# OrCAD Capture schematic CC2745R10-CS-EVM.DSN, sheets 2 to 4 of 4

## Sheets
2 2_Peripherals: size A3
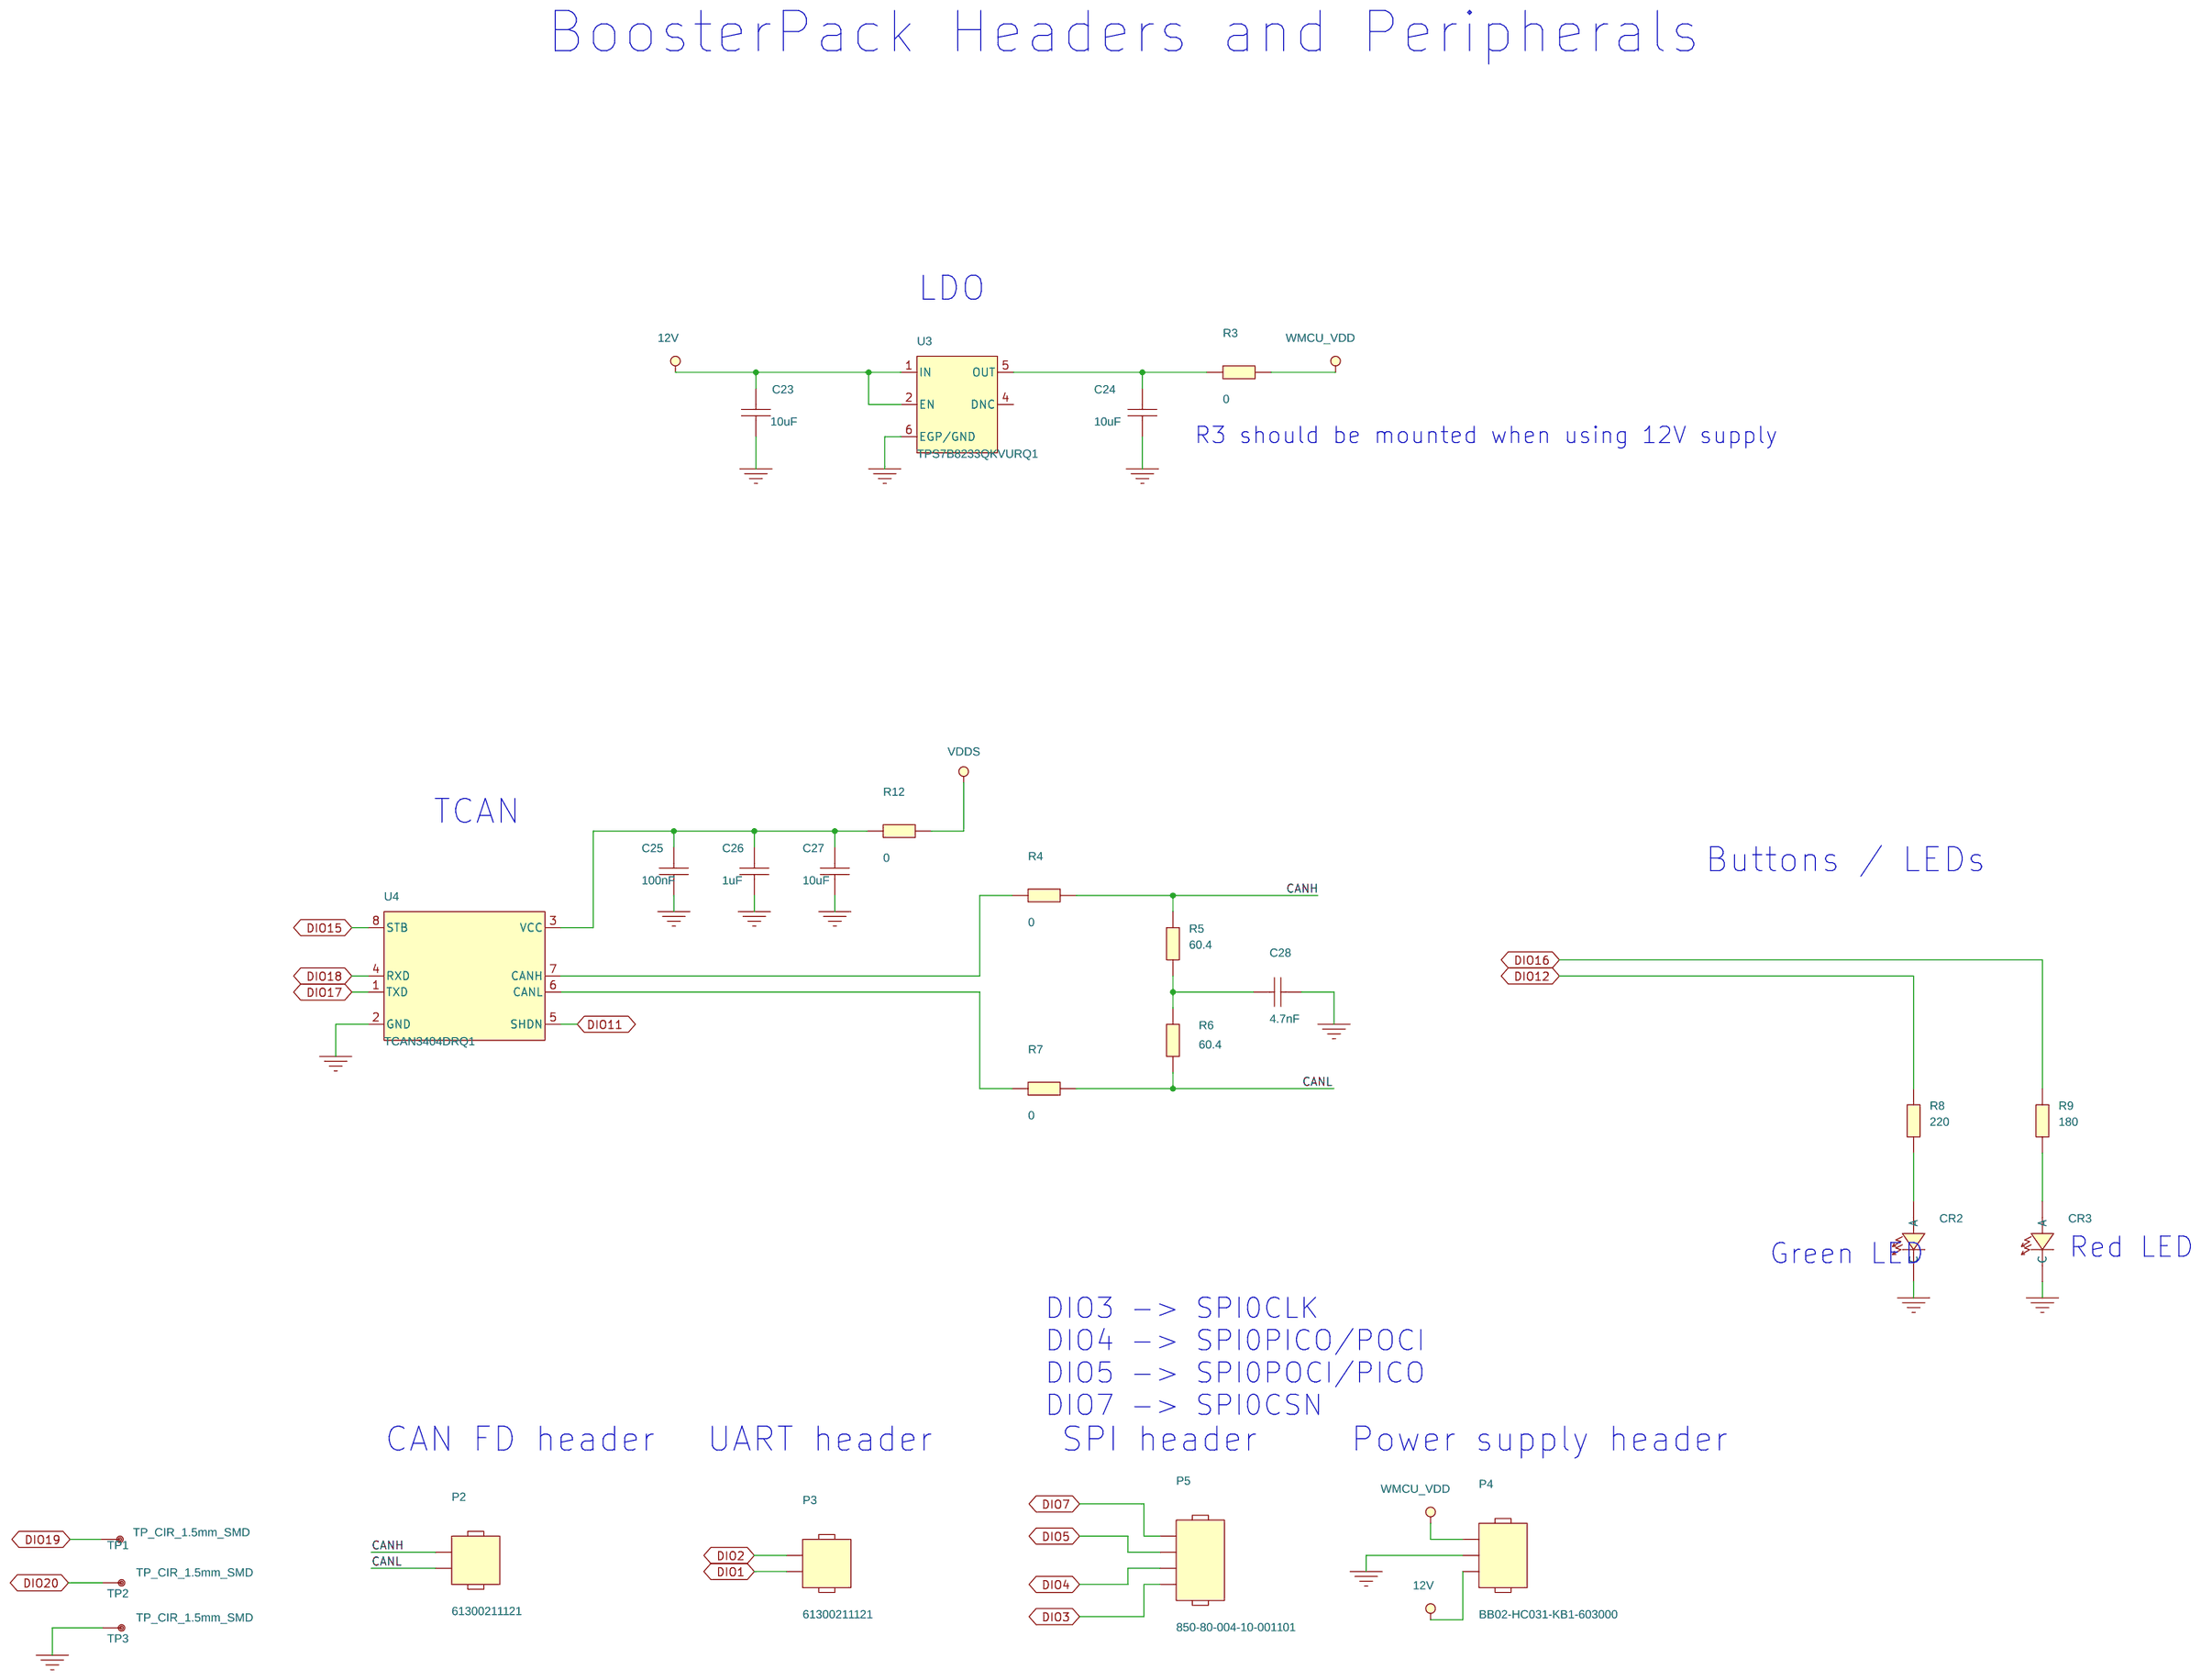
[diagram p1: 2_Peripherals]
3 3_Debugger Interface: size A3
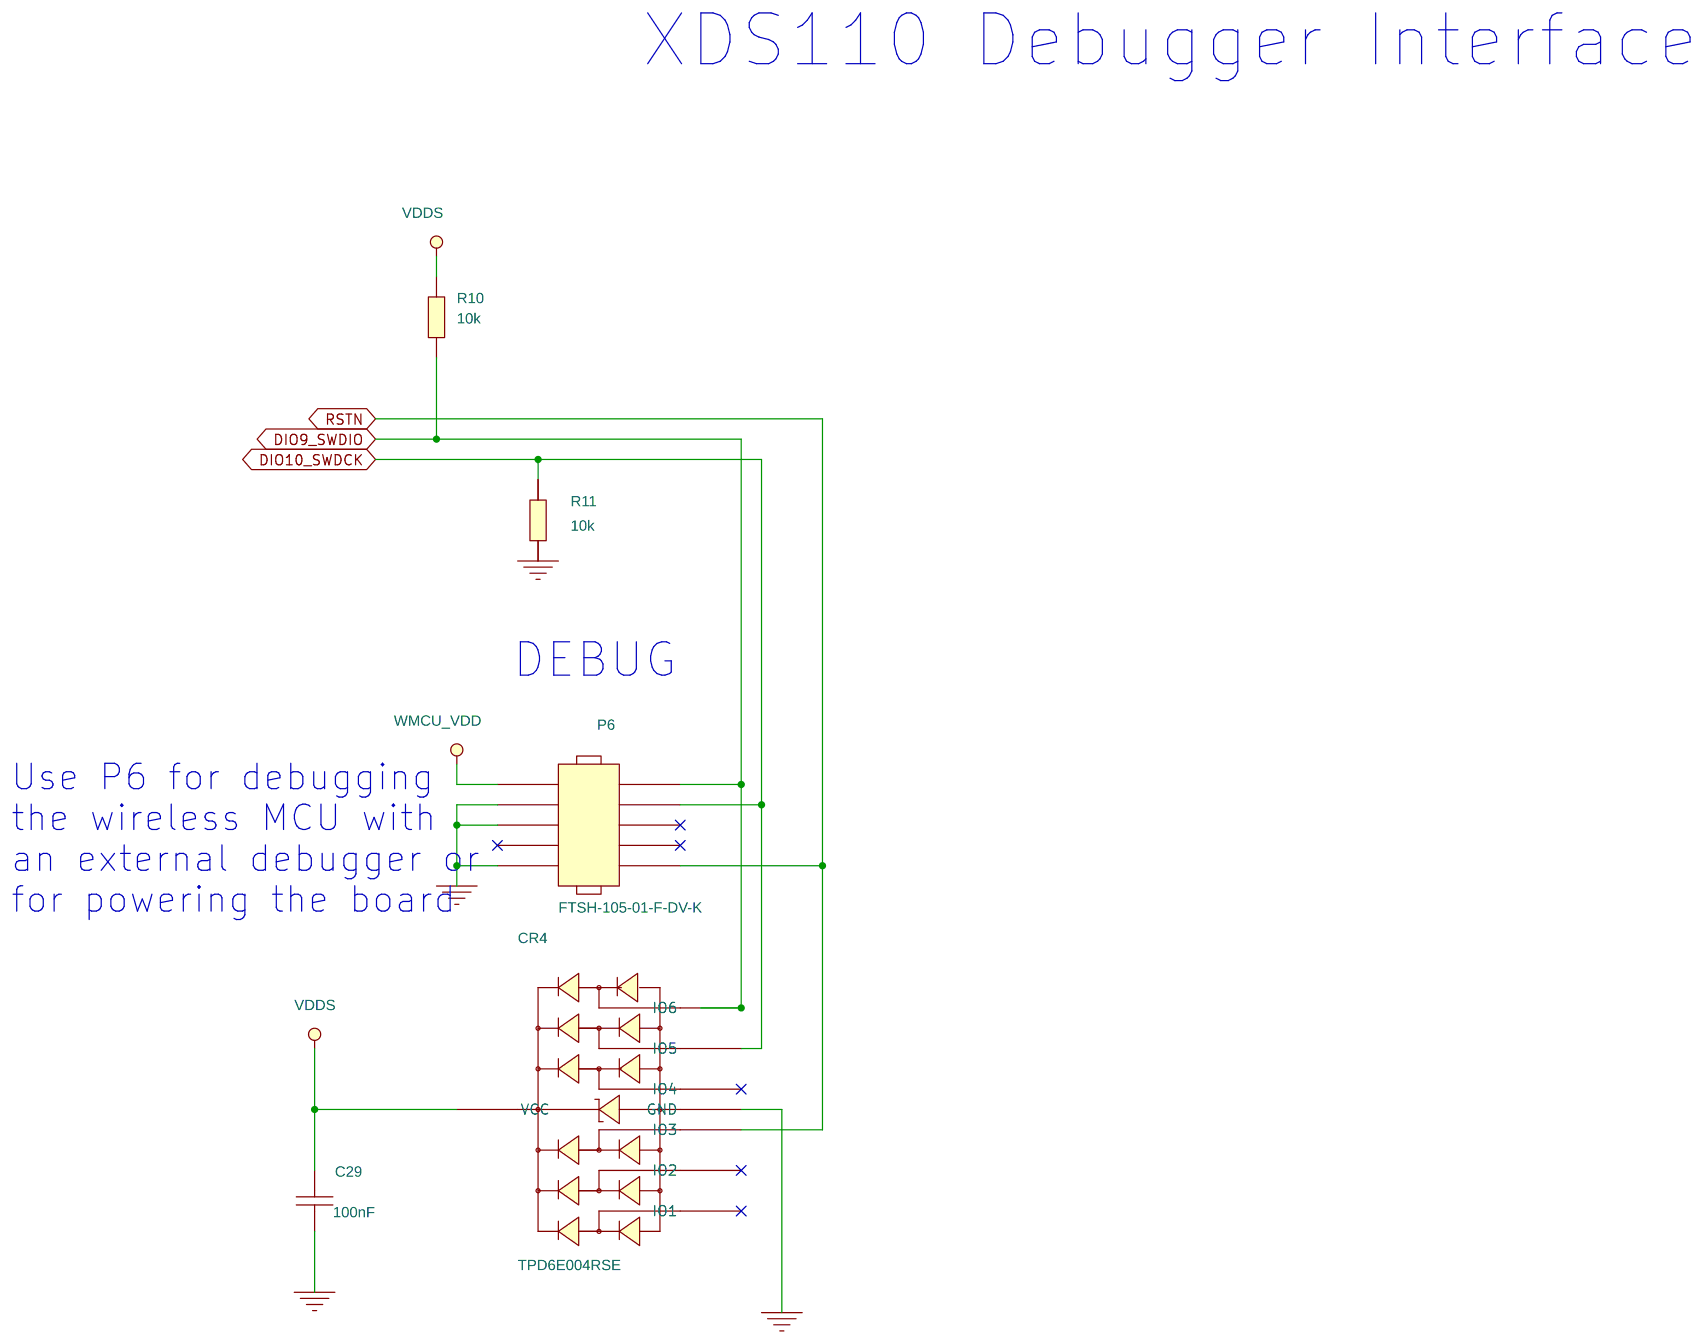
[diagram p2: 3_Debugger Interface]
4 4_Mech: size A3
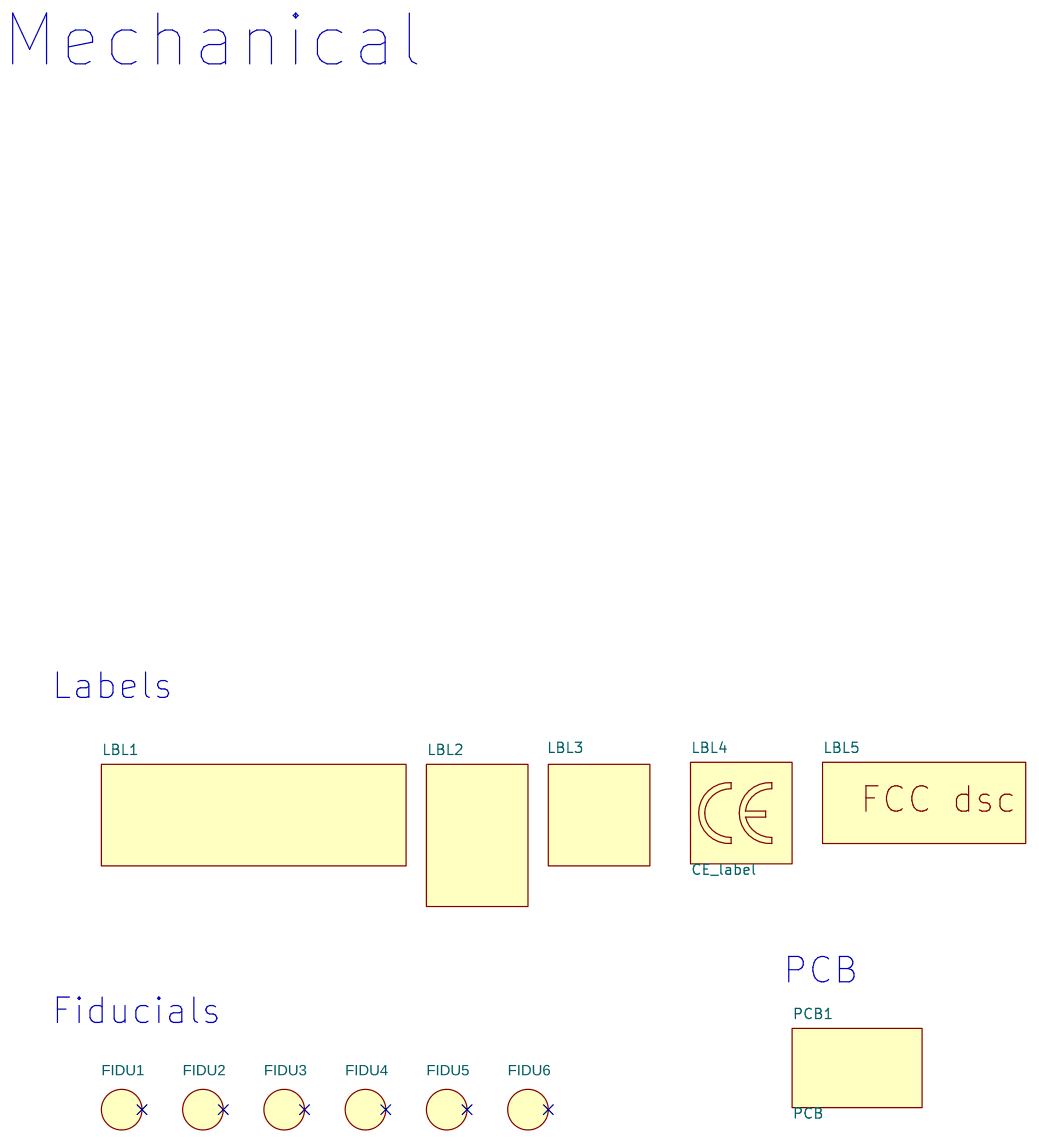
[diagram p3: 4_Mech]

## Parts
sheet 2_Peripherals
C23  10uF  [CAPC2012X150A2N]
C24  10uF  [CAPC1608X100A2N]
C25  100nF  [CAPC0603X35B2N]
C26  1uF  [CAPC1005X60B2N]
C27  10uF  [CAPC1608X100A2N]
C28  4.7nF  [CAPC1005X60A2N]
CR2  150060VS55040  [LEDC1608X50F2N]
CR3  150060RS55040  [LEDC1608X50F2N]
P2  61300211121  [WURTH_61300211121_A2B]
P3  61300211121  [WURTH_61300211121_A2B]
P4  BB02-HC031-KB1-603000  [GRADCONN_BB02HC031KB1603000_A2B]
P5  850-80-004-10-001101  [PRECIDIP_8508000410001101_A2B]
R3  0  [RESC1608X55A2N]
R4  0  [RESC0603X35B2N]
R5  60.4  [RESC1005X40A2N]
R6  60.4  [RESC1005X40A2N]
R7  0  [RESC0603X35B2N]
R8  220  [RESC1005X40B2N]
R9  180  [RESC1005X40B2N]
R12  0  [RESC0603X35B2N]
TP1  TP_CIR_1.5mm_SMD  [TP1500]
TP2  TP_CIR_1.5mm_SMD  [TP1500]
TP3  TP_CIR_1.5mm_SMD  [TP1500]
U3  TPS7B8233QKVURQ1  [TO114P1011X252-6_5A2N]
U4  TCAN3404DRQ1  [SOIC127P600X175-8A2N]
sheet 3_Debugger Interface
C29  100nF  [CAPC0603X35B2N]
CR4  TPD6E004RSE  [QFNFC50P150X150X60-8A2N]
P6  FTSH-105-01-F-DV-K  [SAMTEC_FTSH-105-01-F-DV-K-10N]
R10  10k  [RESC1005X40B2N]
R11  10k  [RESC1005X40B2N]
sheet 4_Mech
FIDU1  FIDU_1.27mm  [FID127X142]
FIDU2  FIDU_1.27mm  [FID127X142]
FIDU3  FIDU_1.27mm  [FID127X142]
FIDU4  FIDU_1.27mm  [FID127X142]
FIDU5  FIDU_1.27mm  [FID127X142]
FIDU6  FIDU_1.27mm  [FID127X142]
LBL1  TI_LOGO  [TI_LOGO_1]
LBL2  TRASH_7mm  [TRASH_7MM]
LBL3  ESD_LABEL_5x5mm  [ESD_LABEL_5X5]
LBL4  CE_label  [CE_MARKING]
LBL5  LABEL_FOR_EVALUATION_ONLY  [LABEL_FOR_EVALUATION_ONLY]
PCB1  PCB  [TI_MCUXX]

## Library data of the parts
C23 = CAPACITOR: CAPACITOR, CERAMIC X7S, 10uF, 25V, -10%/+10%, -55DEGC/+125DEGC, 0805, SMD; ALT_SYMBOLS: CAPC2012X150A2L,CAPC2012X150A2M; Additional Datasheet URL: https://product.samsungsem.com/mlcc/CL21Y106KABVPN.do; Budgetary Price: .181 USD; Country of Origin: China, South Korea; Datasheet URL: https://www.samsungsem.com/resources/file/global/support/product_catalog/MLCC_Automotive.pdf; Dielectric Type: X7S; Lead Time: 20; Mass: N/A; Maximum Operating Temperature: +125DEGC; Maximum Tolerance: +10%; Minimum Operating Temperature: -55DEGC; Minimum Tolerance: -10%; Mounting Type: SMD; NOTEfied URL: https://dev-webinterface.dpserver.no/item/61932654; PCB Package: 0805; Packing Size: 2000; Packing Type: Tape & Reel; Part Number: 02-11587; Part Type: Capacitor|CERAMIC|0805|STANDARD; REACH/SVHC Details: SVHC List Version; ROHS: Compliant; Rated Voltage: 25V; Status: Released; Type: Capacitor; Vendor: SAMSUNG ELECTRO-MECHANICS; Vendor Part Number: CL21Y106KABVPNE; Vendor Part Status: Active
C24 C27 = CAPACITOR: CAPACITOR, CERAMIC X7T, 10uF, 10V, -20%/+20%, -55DEGC/+125DEGC, 0603, SMD; ALT_SYMBOLS: CAPC1608X100A2L,CAPC1608X100A2M; Additional Datasheet URL: https://www.murata.com/en-eu/products/productdetail?partno=GRT188D71A106ME13%23; Country of Origin: Missing Info; Datasheet URL: https://search.murata.co.jp/Ceramy/image/img/A01X/G101/ENG/GRT188D71A106ME13-01A.pdf; Dielectric Type: X7T; Mass: 0.0091g; Maximum Operating Temperature: +125DEGC; Maximum Tolerance: +20%; Minimum Operating Temperature: -55DEGC; Minimum Tolerance: -20%; Mounting Type: SMD; NOTEfied URL: https://notefied-dynamic-precision.com/NOTEfiedWebInterface/part/show?partNumber=02-10485; PCB Package: 0603; Packing Size: 4000; Packing Type: Tape & Reel; Part Number: 02-10485; Part Type: Capacitor|CERAMIC|0603|STANDARD; REACH/SVHC Compliance: Compliant; REACH/SVHC Details: SVHC List Version Jul 08, 2021; REACH/SVHC Source: REACH Declaration; REACH/SVHC Status: Unaffected; ROHS: Compliant; Rated Voltage: 10V; Revision: R010; Status: Released; Texas Part Status: Under Review; Type: Capacitor; Vendor: MURATA; Vendor Part Number: GRT188D71A106ME13D; Vendor Part Status: Active
C25 C29 = CAPACITOR: CAPACITOR, CERAMIC X8M, 100nF, 10V, -10%/+10%, -55DEGC/+150DEGC, 0201, SMD; ALT_SYMBOLS: CAPC0603X35B2L,CAPC0603X35B2M; Additional Datasheet URL: https://www.murata.com/en-us/products/productdetail?partno=GCM033M8ED104KE07%23; Budgetary Price: .01502 USD; Country of Origin: Missing Info; Datasheet URL: https://search.murata.co.jp/Ceramy/image/img/A01X/G101/ENG/GCM033M8ED104KE07-01A.pdf; Dielectric Type: X8M; Lead Time: 23; Mass: 0.00033g; Maximum Operating Temperature: +150DEGC; Maximum Tolerance: +10%; Minimum Operating Temperature: -55DEGC; Minimum Tolerance: -10%; Mounting Type: SMD; NOTEfied URL: https://dev-webinterface.dpserver.no/item/60514337; PCB Package: 0201; Packing Size: 15000; Packing Type: Tape & Reel; Part Number: 02-11497; Part Type: Capacitor|CERAMIC|0201|STANDARD; ROHS: Compliant; Rated Voltage: 10V; Status: Released; Texas Part Status: Under Review; Type: Capacitor; Vendor: MURATA; Vendor Part Number: GCM033M8ED104KE07D; Vendor Part Status: Active
C26 = CAPACITOR: CAPACITOR, CERAMIC X7R, 1uF, 6.3V, -10%/+10%, -55DEGC/+125DEGC, 0402, SMD; Additional Datasheet URL: https://www.murata.com/en-eu/products/productdetail?partno=GRT155R70J105KE01%23; Country of Origin: Missing Info; Datasheet URL: https://search.murata.co.jp/Ceramy/image/img/A01X/G101/ENG/GRT155R70J105KE01-01A.pdf; Dielectric Type: X7R; Mass: 0.0016g; Maximum Operating Temperature: +125DEGC; Maximum Tolerance: +10%; Minimum Operating Temperature: -55DEGC; Minimum Tolerance: -10%; Mounting Type: SMD; NOTEfied URL: https://notefied-dynamic-precision.com/NOTEfiedWebInterface/part/show?partNumber=02-10519; PCB Package: 0402; Packing Size: 10000; Packing Type: Tape & Reel; Part Number: 02-10519; Part Type: Capacitor|CERAMIC|0402|STANDARD; REACH/SVHC Compliance: Compliant; REACH/SVHC Details: SVHC List Version Jul 08, 2021; REACH/SVHC Source: REACH Declaration; REACH/SVHC Status: Unaffected; ROHS: Compliant; Rated Voltage: 6.3V; Revision: R010; Status: Released; Texas Part Status: Under Review; Type: Capacitor; Vendor: MURATA; Vendor Part Number: GRT155R70J105KE01D; Vendor Part Status: Active
C28 = CAPACITOR: CAPACITOR, CERAMIC X7R, 4.7nF, 50V, -10%/+10%, -55DEGC/+125DEGC, 0402, SMD; ALT_SYMBOLS: CAPC1005X60A2L,CAPC1005X60A2M; Additional Datasheet URL: https://www.murata.com/en-us/products/productdetail?partno=GCM155R71H472KA37%23; Budgetary Price: .00716 USD; Country of Origin: China, Japan; Datasheet URL: https://search.murata.co.jp/Ceramy/image/img/A01X/G101/ENG/GCM155R71H472KA37-01A.pdf; Dielectric Type: X7R; Lead Time: 15; Mass: 0.0016g; Maximum Operating Temperature: +125DEGC; Maximum Tolerance: +10%; Minimum Operating Temperature: -55DEGC; Minimum Tolerance: -10%; Mounting Type: SMD; NOTEfied URL: https://dev-webinterface.dpserver.no/item/14049570; PCB Package: 0402; Packing Size: 10000; Packing Type: Tape & Reel; Part Number: 02-08594; Part Type: Capacitor|CERAMIC|0402|STANDARD; ROHS: Compliant; Rated Voltage: 50V; Status: Released; Type: Capacitor; Vendor: MURATA; Vendor Part Number: GCM155R71H472KA37D; Vendor Part Status: Active
CR2 = LED: OPTO, LED, AlInGaP, GREEN, STRAIGHT, 573nm, 2V, 0.02A, 0.048W, 0603, SMD; ALT_SYMBOLS: LEDC1608X50F2L,LEDC1608X50F2M; Additional Datasheet URL: https://www.we-online.com/en/components/products/WL-SMCD#150060VS55040; Country of Origin: Missing Info; Datasheet URL: https://www.we-online.com/en/components/products/datasheet/150060VS55040.pdf; Mass: N/A; Maximum Operating Temperature: +85DEGC; Minimum Operating Temperature: -40DEGC; Mounting Type: SMD; NOTEfied URL: https://notefied-dynamic-precision.com/NOTEfiedWebInterface/part/show?partNumber=15-03575; PCB Package: 0603; Packing Size: 4000; Packing Type: Tape & Reel; Part Number: 15-03575; Part Type: Opto|LED|0603; REACH/SVHC Details: SVHC List Version; ROHS: Compliant; Rated Current: 0.02A; Rated Power: 0.048W; Rated Voltage: 2V; Revision: R008; Status: Released; Type: Opto; Vendor: WURTH; Vendor Part Status: Active
CR3 = LED: OPTO, LED, AlInGaP, RED, STRAIGHT, 624nm, 2V, 0.02A, 0.048W, 0603, SMD; ALT_SYMBOLS: LEDC1608X50F2L,LEDC1608X50F2M; Additional Datasheet URL: https://www.we-online.com/en/components/products/WL-SMCD#150060RS55040; Country of Origin: Missing Info; Datasheet URL: https://www.we-online.com/en/components/products/datasheet/150060RS55040.pdf; Mass: N/A; Maximum Operating Temperature: +85DEGC; Minimum Operating Temperature: -40DEGC; Mounting Type: SMD; NOTEfied URL: https://notefied-dynamic-precision.com/NOTEfiedWebInterface/part/show?partNumber=15-03577; PCB Package: 0603; Packing Size: 4000; Packing Type: Tape & Reel; Part Number: 15-03577; Part Type: Opto|LED|0603; REACH/SVHC Details: SVHC List Version; ROHS: Compliant; Rated Current: 0.02A; Rated Power: 0.048W; Rated Voltage: 2V; Revision: R008; Status: Released; Type: Opto; Vendor: WURTH; Vendor Part Status: Active
P2 P3 = CONN_HEADER_2_P_S: CONNECTOR, HEADER, MALE, STRAIGHT, 1 ROW(S), 2 PIN(S), PITCH 2.54mm, PTH; ALT_SYMBOLS: WURTH_61300211121_A2A,WURTH_61300211121_A2C; Additional Datasheet URL: https://www.we-online.com/en/components/products/PHD_2_54_THT_PIN_HEADER_6130XX11121?sq=61300211121#61300211121; Budgetary Price: .06 USD; Country of Origin: Taiwan; Datasheet URL: https://www.we-online.com/components/products/datasheet/61300211121.pdf; Lead Time: 13; Mass: N/A; Maximum Operating Temperature: +105DEGC; Minimum Operating Temperature: -40DEGC; Mounting Type: PTH; NOTEfied URL: https://dev-webinterface.dpserver.no/item/62668710; Number of Positions: 2; Number of Rows: 1; Packing Size: 1000; Packing Type: Bag; Part Number: 06-16671; Part Type: Connector|HEADER|STANDARD; Pitch: 2.54mm; REACH/SVHC Compliance: Compliant; REACH/SVHC Details: SVHC List Version Nov 07, 2024 (242); REACH/SVHC Source: REACH Declaration; REACH/SVHC Status: Unaffected; ROHS: Compliant; Rated Current: 3A; Rated Voltage: 250V; Status: Released; Texas Part Status: Under Review; Type: Connector; Vendor: WURTH; Vendor Part Status: Active
P4 = CONN_HEADER_3_P_S: CONNECTOR, HEADER, MALE, STRAIGHT, 1 ROW(S), 3 PIN(S), PITCH 2.54mm, PTH; ALT_SYMBOLS: GRADCONN_BB02HC031KB1603000_A2A,GRADCONN_BB02HC031KB1603000_A2C; Additional Datasheet URL: https://www.gradconn.com/Products/BoardToBoard/All/BB02-HC; Country of Origin: Missing Info; Datasheet URL: https://www.gradconn.com/files/Drawings/BB02-HC.pdf; Mass: N/A; Maximum Operating Temperature: +105DEGC; Minimum Operating Temperature: -40DEGC; Mounting Type: PTH; NOTEfied URL: https://dev-webinterface.dpserver.no/item/7324030; Number of Positions: 3; Number of Rows: 1; Packing Size: N/A; Packing Type: Missing Info; Part Number: 06-05038; Part Type: Connector|HEADER|STANDARD; Pitch: 2.54mm; REACH/SVHC Compliance: Compliant; REACH/SVHC Details: SVHC List Version Jun 20, 2016 (169); REACH/SVHC Source: RoHS & REACH Declaration; REACH/SVHC Status: Unaffected; ROHS: Compliant; Rated Current: 3A; Rated Voltage: 250V; Status: Released; Texas Part Status: Under Review; Type: Connector; Vendor: GRADCONN; Vendor Part Status: Active
P5 = CONN_HEADER_4_P_S: CONNECTOR, HEADER, MALE, STRAIGHT, 1 ROW(S), 4 PIN(S), PITCH 1.27mm, PTH; ALT_SYMBOLS: PRECIDIP_8508000410001101_A2A,PRECIDIP_8508000410001101_A2C; Additional Datasheet URL: https://precidip.com/product/850-80-004-10-001101/; Budgetary Price: .5229 USD; Country of Origin: Switzerland; Datasheet URL: https://precidip.com/wp-content/uploads/2024/10/Full-English.pdf; Lead Time: 11; Mass: N/A; Maximum Operating Temperature: +125DEGC; Minimum Operating Temperature: -55DEGC; Mounting Type: PTH; NOTEfied URL: https://dev-webinterface.dpserver.no/item/62648482; Number of Positions: 4; Number of Rows: 1; Packing Size: N/A; Packing Type: Missing Info; Part Number: 06-16651; Part Type: Connector|HEADER|STANDARD; Pitch: 1.27mm; REACH/SVHC Compliance: Non-Compliant; REACH/SVHC Details: SVHC List Version Jan 21, 2025 (247); REACH/SVHC Source: REACH Declaration; REACH/SVHC Status: Affected; ROHS: Compliant; Rated Current: 1A; Rated Voltage: N/A; Status: Released; Texas Part Status: Under Review; Type: Connector; Vendor: PRECI-DIP; Vendor Part Status: Active
R3 = RESISTOR: RESISTOR, THICK FILM, JUMPER, 0, 0R/+0.05R, 0.1W, 1A, -55DEGC/+155DEGC, 0603, SMD; ALT_SYMBOLS: RESC1608X55A2L,RESC1608X55A2M; Additional Datasheet URL: https://www.yageo.com/en/ProductSearch/PartNumberSearch?part_number=AC0603JR-070RL; Budgetary Price: .00383 USD; Country of Origin: China, Taiwan; Datasheet URL: https://www.yageo.com/upload/media/product/productsearch/datasheet/rchip/PYu-AC_51_RoHS_L_11.pdf; Lead Time: 18; Mass: N/A; Maximum Operating Temperature: +155DEGC; Maximum Temperature Coefficient: N/A; Maximum Tolerance: +0.05R; Minimum Operating Temperature: -55DEGC; Minimum Temperature Coefficient: N/A; Minimum Tolerance: 0R; Mounting Type: SMD; NOTEfied URL: https://dev-webinterface.dpserver.no/item/58001233; PCB Package: 0603; Packing Size: 5000; Packing Type: Tape & Reel; Part Number: 01-26111; Part Type: Resistor|0603|JUMPER; REACH/SVHC Details: SVHC List Version; ROHS: Exempt; Rated Current: 1A; Rated Power: 0.1W; Rated Voltage: N/A; Resistor Type: THICK FILM; Status: Released; Type: Resistor; Vendor: YAGEO; Vendor Part Number: AC0603JR-070RL; Vendor Part Status: Active
R4 R7 R12 = RESISTOR: RESISTOR, THICK FILM, JUMPER, 0, 0R/+0.05R, 0.05W, 0.5A, -55DEGC/+155DEGC, 0201, SMD; ALT_SYMBOLS: RESC0603X35B2L,RESC0603X35B2M; Additional Datasheet URL: https://www.yageo.com/en/Home; Budgetary Price: .01936 USD; Country of Origin: Missing Info; Datasheet URL: https://www.yageo.com/upload/media/product/productsearch/datasheet/rchip/PYu-AF_51_RoHS_L_10.pdf; Lead Time: 18; Mass: N/A; Maximum Operating Temperature: +155DEGC; Maximum Temperature Coefficient: N/A; Maximum Tolerance: +0.05R; Minimum Operating Temperature: -55DEGC; Minimum Temperature Coefficient: N/A; Minimum Tolerance: 0R; Mounting Type: SMD; NOTEfied URL: https://dev-webinterface.dpserver.no/item/59954582; PCB Package: 0201; Packing Size: 50000; Packing Type: Tape & Reel; Part Number: 01-26238; Part Type: Resistor|0201|JUMPER; ROHS: Exempt; Rated Current: 0.5A; Rated Power: 0.05W; Resistor Type: THICK FILM; Status: Released; Texas Part Status: Under Review; Type: Resistor; Vendor: YAGEO; Vendor Part Number: AF0201JR-130RL; Vendor Part Status: Active
R5 R6 = RESISTOR: RESISTOR, THICK FILM, 60.4, -1%/+1%, 0.1W, 50V, -55DEGC/+155DEGC, 0402, SMD; ALT_SYMBOLS: RESC1005X40A2L,RESC1005X40A2M; Additional Datasheet URL: https://industrial.panasonic.com/ww/products/pt/general-purpose-chip-resistors/models/ERJ2RKF60R4X; Budgetary Price: .00413 USD; Country of Origin: Japan; Datasheet URL: https://industrial.panasonic.com/cdbs/www-data/pdf/RDA0000/AOA0000C304.pdf; Lead Time: 11; Mass: 0.0008g; Maximum Operating Temperature: +155DEGC; Maximum Temperature Coefficient: +100PPM/DEGC; Maximum Tolerance: +1%; Minimum Operating Temperature: -55DEGC; Minimum Temperature Coefficient: -100PPM/DEGC; Minimum Tolerance: -1%; Mounting Type: SMD; NOTEfied URL: https://dev-webinterface.dpserver.no/item/7238508; PCB Package: 0402; Packing Size: 10000; Packing Type: Tape & Reel; Part Number: 01-17773; Part Type: Resistor|0402|PRECISION; ROHS: Exempt; Rated Current: N/A; Rated Power: 0.1W; Rated Voltage: 50V; Resistor Type: THICK FILM; Status: Released; Type: Resistor; Vendor: PANASONIC INDUSTRIAL; Vendor Part Number: ERJ2RKF60R4X; Vendor Part Status: Active
R8 = RESISTOR: RESISTOR, THICK FILM, 220, -5%/+5%, 0.063W, 50V, -55DEGC/+155DEGC, 0402, SMD; Additional Datasheet URL: https://www.vishay.com/en/product/20035/; AutoDoc File: https://notefied-dynamic-precision.com/DB/Apps/Desktop/Item/Object.aspx?id=113319; BU Name: TEXAS INSTRUMENTS NORWAY; Budget Currency: EUR; Budget Price: 0.014; Budgetary Price: 0.014 EUR; Client Status: UNDER_REVIEW; Country of Origin: China,Israel; Datasheet URL: https://www.vishay.com/docs/20035/dcrcwe3.pdf; Datasheet URL 1: http://www.vishay.com/docs/20035/dcrcwe3.pdf; Datasheet URL 2: N/A; Definied Quality: INDUSTRIAL; Esd Level: N/A; Lead Time: 18; LifeCycle Status: ACTIVE; MPN: RESISTOR_0402_220_+/-5%_50V_0.063W_M_+/-200ppm; MPN Status: ACTIVE; MSL: N/A; MTBF: N/A; MTBF Standard: N/A; Manufacturer: MANUFACTURER SELECTION; Mass: 0.00065g; Max Oper Temp: +155DEGC; Max TC: +200PPM/DEGC; Max Tol: +5%; Maximum Operating Temperature: +155DEGC; Maximum Temperature Coefficient: +200PPM/DEGC; Maximum Tolerance: +5%; Min Oper Temp: -55DEGC; Min TC: -200PPM/DEGC; Min Tol: -5%; Minimum Operating Temperature: -55DEGC; Minimum Temperature Coeficient: -200PPM/DEGC; Minimum Tolerance: -5%; Mounting Type: SMD; NOTE Status: PREFERRED; NOTEfied URL: https://notefied-dynamic-precision.com/NOTEfiedWebInterface/part/show?partNumber=01-22346; Notes: Standard item: Duplicate Reason: custom footprint for TEXAS INSTRUMENTS NORWAY.; Old Footprint: RESC1005X40N; PCB Package: 0402; Packing Size: 10000; Packing Type: Tape & Reel; Part Number: 01-22346; Part Type: Resistor|0402|STANDARD; REACH/SVHC Compliance: Compliant; REACH/SVHC Details: SVHC List Version Jun 20, 2016; REACH/SVHC Source: Material Declaration; REACH/SVHC Status: Unaffected; REACH/SVHC_COMPLIANCE: COMPLIANT; REACH/SVHC_DETAILS: SVHC LIST VERSION Jun 20, 2016; REACH/SVHC_SOURCE: MATERIAL DECLARATION; REACH/SVHC_STATUS: UNAFFECTED; ROHS: Exempt; Rated Current: N/A; Rated Power: 0.063W; Rated Voltage: 50V; Resistor Type: THICK FILM; Revision: R034; RoHS Status: ROHS_COMPLIANT_WITH_EXEMPTION; Rtd Current: N/A; Rtd Power: 0.063W; Rtd Voltage: 50V; Status: Released; Texas Part Status: Under Review; Type: Resistor; Vendor: VISHAY; Vendor Part Number: CRCW0402220RJNED; Vendor Part Status: Active; WEIGHT: 0.00065g
R9 = RESISTOR: RESISTOR, THICK FILM, 180, -5%/+5%, 0.063W, 50V, -55DEGC/+155DEGC, 0402, SMD; Additional Datasheet URL: https://www.vishay.com/en/product/20035/; AutoDoc File: https://notefied-dynamic-precision.com/DB/Apps/Desktop/Item/Object.aspx?id=113318; BU Name: TEXAS INSTRUMENTS NORWAY; Budget Currency: EUR; Budget Price: 0.014; Budgetary Price: 0.014 EUR; Client Status: UNDER_REVIEW; Country of Origin: China,Israel; Datasheet URL: https://www.vishay.com/docs/20035/dcrcwe3.pdf; Datasheet URL 1: http://www.vishay.com/docs/20035/dcrcwe3.pdf; Datasheet URL 2: N/A; Definied Quality: INDUSTRIAL; Esd Level: N/A; Lead Time: 18; LifeCycle Status: ACTIVE; MPN: RESISTOR_0402_180_+/-5%_50V_0.063W_M_+/-200ppm; MPN Status: ACTIVE; MSL: N/A; MTBF: N/A; MTBF Standard: N/A; Manufacturer: MANUFACTURER SELECTION; Mass: 0.00065g; Max Oper Temp: +155DEGC; Max TC: +200PPM/DEGC; Max Tol: +5%; Maximum Operating Temperature: +155DEGC; Maximum Temperature Coefficient: +200PPM/DEGC; Maximum Tolerance: +5%; Min Oper Temp: -55DEGC; Min TC: -200PPM/DEGC; Min Tol: -5%; Minimum Operating Temperature: -55DEGC; Minimum Temperature Coeficient: -200PPM/DEGC; Minimum Tolerance: -5%; Mounting Type: SMD; NOTE Status: PREFERRED; NOTEfied URL: https://notefied-dynamic-precision.com/NOTEfiedWebInterface/part/show?partNumber=01-22345; Notes: Standard item: Duplicate Reason: custom footprint for TEXAS INSTRUMENTS NORWAY.; Old Footprint: RESC1005X40N; PCB Package: 0402; Packing Size: 10000; Packing Type: Tape & Reel; Part Number: 01-22345; Part Type: Resistor|0402|STANDARD; REACH/SVHC Compliance: Compliant; REACH/SVHC Details: SVHC List Version Jun 20, 2016; REACH/SVHC Source: Material Declaration; REACH/SVHC Status: Unaffected; REACH/SVHC_COMPLIANCE: COMPLIANT; REACH/SVHC_DETAILS: SVHC LIST VERSION Jun 20, 2016; REACH/SVHC_SOURCE: MATERIAL DECLARATION; REACH/SVHC_STATUS: UNAFFECTED; ROHS: Exempt; Rated Current: N/A; Rated Power: 0.063W; Rated Voltage: 50V; Resistor Type: THICK FILM; Revision: R034; RoHS Status: ROHS_COMPLIANT_WITH_EXEMPTION; Rtd Current: N/A; Rtd Power: 0.063W; Rtd Voltage: 50V; Status: Released; Texas Part Status: Under Review; Type: Resistor; Vendor: VISHAY; Vendor Part Number: CRCW0402180RJNED; Vendor Part Status: Active; WEIGHT: 0.00065g
TP1-TP3 = TEST_POINT: NON COMPONENT, TEST POINT, CIRCULAR 1.5mm, SMD; Additional Datasheet URL: N/A; Country of Origin: Missing Info; Datasheet URL: N/A; Mass: N/A; Maximum Operating Temperature: N/A; Minimum Operating Temperature: N/A; Mounting Type: SMD; NOTEfied URL: https://webinterface.notefied-dynamic-precision.com/item/7503653; Packing Size: N/A; Packing Type: Missing Info; Part Number: 19-00115; Part Type: Non Component|TEST POINT; ROHS: Not Applicable; Status: Released; Type: Non Component; Vendor: NON_COMPONENT; Vendor Part Status: Active
U3 = IC_PM_TPS7B82-Q1_TO-252-5: IC, ANALOG, 0.3A AUTOMOTIVE, HIGH-VOLTAGE, ULTRA-LOW-IQ LOW-DROPOUT REGULATOR, VIN:3V TO 40V, TO-252-5, SMD; ALT_SYMBOLS: TO114P1011X252-6_5A2L,TO114P1011X252-6_5A2M; Additional Datasheet URL: https://www.ti.com/product/TPS7B82-Q1/part-details/TPS7B8233QKVURQ1; Budgetary Price: .627 USD; Country of Origin: China; Datasheet URL: https://www.ti.com/lit/ds/symlink/tps7b82-q1.pdf; Lead Time: 6; Mass: 0.370164642g; Maximum Operating Temperature: +150DEGC; Minimum Operating Temperature: -40DEGC; Mounting Type: SMD; NOTEfied URL: https://dev-webinterface.dpserver.no/item/62213188; PCB Package: TO-252-5; Packing Size: 2500; Packing Type: Tape & Reel; Part Number: 18-39569; Part Type: IC|ANALOG|PM|REGULATOR; REACH/SVHC Compliance: Compliant; REACH/SVHC Details: SVHC List Version Jan 21, 2025 (247); REACH/SVHC Source: REACH Declaration; REACH/SVHC Status: Unaffected; ROHS: Compliant; Rated Current: 0.3A; Status: Released; Texas Part Status: Under Review; Type: IC; Vendor: TEXAS INSTRUMENTS; Vendor Part Status: Active
U4 = IC_PERIPH_TCAN3404_SOT23-8: IC, DIGITAL, AUTOMOTIVE CAN FD TRANSCEIVER WITH STANDBY MODE, 3V TO 3.6V, SO8, SMD; ALT_SYMBOLS: SOIC127P600X175-8A2L,SOIC127P600X175-8A2M; Additional Datasheet URL: https://www.ti.com/product/TCAN3404-Q1/part-details/TCAN3404DRQ1; Budgetary Price: .52 USD; Country of Origin: Mexico; Datasheet URL: https://www.ti.com/lit/ds/symlink/tcan3404-q1.pdf; Lead Time: 18; Mass: 0.075896327g; Maximum Operating Temperature: +150DEGC; Minimum Operating Temperature: -40DEGC; Mounting Type: SMD; NOTEfied URL: https://dev-webinterface.dpserver.no/item/62093787; PCB Package: SO8; Packing Size: 2500; Packing Type: Tape & Reel; Part Number: 18-39547; Part Type: IC|DIGITAL|INTERFACE|CAN; REACH/SVHC Compliance: Compliant; REACH/SVHC Details: SVHC List Version Nov 07, 2024 (242); REACH/SVHC Source: REACH Declaration; REACH/SVHC Status: Unaffected; ROHS: Compliant; Status: Released; Texas Part Status: Under Review; Type: IC; Vendor: TEXAS INSTRUMENTS; Vendor Part Status: Active
CR4 = DIODE_TVS_TPD6E004_QFN8_V1: DIODE, PROTECTION, ESD ARRAY - 6 CHANNELS, 0.9V TO 5.5V, VBR:7V, -40DEGC/+85DEGC, QFN8, SMD; ALT_SYMBOLS: QFNFC50P150X150X60-8A2L,QFNFC50P150X150X60-8A2M; Additional Datasheet URL: https://www.ti.com/product/TPD6E004/part-details/TPD6E004RSER; AutoDoc File: https://notefied-dynamic-precision.com/DB/Apps/Desktop/Item/Object.aspx?id=74721; BU Name: DYNAMIC PRECISION GDANSK; Budget Currency: USD; Budget Price: 0.27; Budgetary Price: 0.295 USD; CLASS: IC; Client Status: UNDER_REVIEW; Country of Origin: China,Thailand; Datasheet URL: https://www.ti.com/lit/ds/symlink/tpd6e004.pdf; Datasheet URL 1: http://www.ti.com/lit/ds/symlink/tpd6e004.pdf; Datasheet URL 2: http://www.ti.com/litv/pdf/mpqf207b; FPLIST: QFN50P150X150X60-8N,QFN50P150X150X60-8AN; Lead Time: 10; Mass: 0.0033g; Max Oper Temp: +85DEGC; Maximum Operating Temperature: +85DEGC; Min Oper Temp: -40DEGC; Minimum Operating Temperature: -40DEGC; Mounting Type: SMD; NOTEfied URL: https://notefied-dynamic-precision.com/NOTEfiedWebInterface/part/show?partNumber=14-05493; PCB Package: QFN8; Packing Size: 3000; Packing Type: Tape & Reel; Part Number: 14-05493; Part Type: Diode|PROTECTION; REACH/SVHC Compliance: Compliant; REACH/SVHC Details: SVHC List Version Jun 20, 2016; REACH/SVHC Source: Material Declaration; REACH/SVHC Status: Unaffected; ROHS: Compliant; Rated Power: N/A; Rated Voltage: 7V; Revision: R039; RoHS Status: ROHS_COMPLIANT; Rtd Power: N/A; Rtd Voltage: 7V; Status: Released; Texas Part Status: Under Review; Type: Diode; Vendor: TEXAS INSTRUMENTS; Vendor Part Number: TPD6E004RSER; Vendor Part Status: Active; Weight: 0.0033g
P6 = CONN_HEADER_2X5: CONNECTOR, HEADER, MALE, STRAIGHT, 2 ROW(S), 10 PIN(S), PITCH 1.27mm, SMD; ALT_SYMBOLS: SAMTEC_FTSH10501FDVK_A2L,SAMTEC_FTSH10501FDVK_A2M,SAMTEC_FTSH10501FDVK_B2M,SAMTEC_FTSH10501FDVK_B2L; Additional Datasheet URL: https://www.samtec.com/products/ftsh-105-01-f-dv-k; AutoDoc File: http://notefied-dynamic-precision.com/DB/Apps/Desktop/Item/Object.aspx?id=50836; Budget Currency: USD; Budget Price: 1.700; Budgetary Price: 2.07959 USD; CLASS: IO; Country of Origin: China,Costa Rica,Malaysia,Singapore,Taiwan,United States,Vietnam; Datasheet URL: https://suddendocs.samtec.com/catalog_english/ftsh_smt.pdf; Datasheet URL 1: http://www.samtec.com/documents/webfiles/cpdf/FTSH-1XX-XX-XXX-DV-XXX-MKT.pdf; Datasheet URL 2: http://www.samtec.com/documents/webfiles/pdf/FTSH_SMT.PDF; FPLIST: SAMTEC_FTSH10501FDVK_A2N,SAMTEC_FTSH-105-01-F-DV-K-10N; Lead Time: 14; LifeCycle Status: MATURITY; MPN Status: ACTIVE; Manufacturer: SAMTEC; Mass: 0.31700g; Max Oper Temp: +125DEGC; Maximum Operating Temperature: +125DEGC; Min Oper Temp: -55DEGC; Minimum Operating Temperature: -55DEGC; Mounting Type: SMD; NOTE Status: PREFERRED; NOTEfied URL: https://notefied-dynamic-precision.com/NOTEfiedWebInterface/part/show?partNumber=06-00166; No Of Pos: 10; No Of Rows: 2; Number of Positions: 10; Number of Rows: 2; Old Footprint: SAMTEC_FTSH-105-01-F-DV-K-10N,CONN_MALE_2X5; Packing Size: 92; Packing Type: Tube; Part Number: 06-00166; Part Type: Connector|HEADER|STANDARD; Pitch: 1.27mm; REACH/SVHC Compliance: Compliant; REACH/SVHC Details: SVHC List Version Jun 10, 2022; REACH/SVHC Source: REACH Declaration; REACH/SVHC Status: Unaffected; ROHS: Compliant; Rated Current: 3.4A; Revision: R044; RoHS Status: ROHS_COMPLIANT; Rtd Current: 1.75A; Status: Released; Texas Part Status: Under Review; Type: Connector; Vendor: SAMTEC; Vendor Part Status: Active; WEIGHT: 0.65614g
R10 R11 = RESISTOR: RESISTOR, THICK FILM, 10k, -5%/+5%, 0.063W, 50V, -55DEGC/+155DEGC, 0402, SMD; Additional Datasheet URL: https://www.vishay.com/en/product/20035/; Budgetary Price: 0.014 EUR; Country of Origin: China,Israel; Datasheet URL: https://www.vishay.com/docs/20035/dcrcwe3.pdf; Lead Time: 18; Mass: 0.00065g; Maximum Operating Temperature: +155DEGC; Maximum Temperature Coefficient: +200PPM/DEGC; Maximum Tolerance: +5%; Minimum Operating Temperature: -55DEGC; Minimum Temperature Coeficient: -200PPM/DEGC; Minimum Tolerance: -5%; Mounting Type: SMD; NOTEfied URL: https://notefied-dynamic-precision.com/NOTEfiedWebInterface/part/show?partNumber=01-22353; Notes: Standard item: Duplicate Reason: custom footprint for TEXAS INSTRUMENTS NORWAY.; PCB Package: 0402; Packing Size: 10000; Packing Type: Tape & Reel; Part Number: 01-22353; Part Type: Resistor|0402|STANDARD; REACH/SVHC Compliance: Compliant; REACH/SVHC Details: SVHC List Version Jun 20, 2016; REACH/SVHC Source: Material Declaration; REACH/SVHC Status: Unaffected; ROHS: Exempt; Rated Current: N/A; Rated Power: 0.063W; Rated Voltage: 50V; Resistor Type: THICK FILM; Revision: R037; Status: Released; Texas Part Status: Under Review; Type: Resistor; Vendor: VISHAY; Vendor Part Number: CRCW040210K0JNED; Vendor Part Status: Active
FIDU1-FIDU6 = FIDMARK: NON COMPONENT, FIDUCIAL MARK, ROUND 1.27MM, SMD; Additional Datasheet URL: N/A; CLASS: IO; Country of Origin: Missing Info; Datasheet URL: N/A; Mass: N/A; Mounting Type: SMD; NOTEfied URL: https://notefied-dynamic-precision.com/NOTEfiedWebInterface/part/show?partNumber=19-00300; Packing Size: N/A; Packing Type: Missing Info; Part Number: 19-00300; Part Type: Non Component|FIDUCIAL; ROHS: Not Applicable; Revision: R030; Status: Released; Texas Part Status: Under Review; Type: Non Component; Vendor: NON_COMPONENT; Vendor Part Number: FIDUCIAL_1.27mm; Vendor Part Status: Active
LBL1 = TI_LOGO_V1: NON COMPONENT, LABEL, TEXAS INSTRUMENTS LOGO; Additional Datasheet URL: N/A; AutoDoc File: https://notefied-dynamic-precision.com/DB/Apps/Desktop/Item/Object.aspx?id=87770; BU Name: TEXAS INSTRUMENTS NORWAY; Country of Origin: Missing Info; Datasheet URL: N/A; Mass: N/A; Mounting Type: NOT APPLY; NOTEfied URL: https://notefied-dynamic-precision.com/NOTEfiedWebInterface/part/show?partNumber=19-00350; Notes: Custom Item; Packing Size: N/A; Packing Type: Missing Info; Part Number: 19-00350; Part Type: Non Component|LABEL; ROHS: Not Applicable; Revision: R033; Status: Released; Texas Part Status: Under Review; Type: Non Component; Vendor: NON_COMPONENT; Vendor Part Status: Active
LBL2 = TRASH_V2: NON COMPONENT, LABEL, TRASH 7mm; Additional Datasheet URL: N/A; Country of Origin: Missing Info; Datasheet URL: N/A; Mass: N/A; Mounting Type: NOT APPLY; NOTEfied URL: https://notefied-dynamic-precision.com/NOTEfiedWebInterface/part/show?partNumber=19-01044; Packing Size: N/A; Packing Type: Missing Info; Part Number: 19-01044; Part Type: Non Component|LABEL; ROHS: Not Applicable; Revision: R026; Status: Released; Texas Part Status: Under Review; Type: Non Component; Vendor: NON_COMPONENT; Vendor Part Status: Active
LBL3 = ESD_LABEL: NON COMPONENT, LABEL, ESD, 5 X 5 mm; Additional Datasheet URL: N/A; Country of Origin: Missing Info; Datasheet URL: N/A; Mass: N/A; Maximum Operating Temperature: N/A; Minimum Operating Temperature: N/A; Mounting Type: NOT APPLY; NOTEfied URL: https://notefied-dynamic-precision.com/NOTEfiedWebInterface/part/show?partNumber=19-00471; Packing Size: N/A; Packing Type: Missing Info; Part Number: 19-00471; Part Type: Non Component|LABEL; ROHS: Not Applicable; Revision: R010; Status: Released; Type: Non Component; Vendor: NON_COMPONENT; Vendor Part Status: Active
LBL4 = CE_LABEL_V1: NON COMPONENT, LABEL, CE; Additional Datasheet URL: N/A; Country of Origin: Missing Info; Datasheet URL: http://www.ce-marking.com/CE-marking-logo.html; Mass: N/A; Mounting Type: NOT APPLY; NOTEfied URL: https://notefied-dynamic-precision.com/NOTEfiedWebInterface/part/show?partNumber=19-00351; Packing Size: N/A; Packing Type: Missing Info; Part Number: 19-00351; Part Type: Non Component|LABEL; ROHS: Not Applicable; Revision: R035; Status: Released; Texas Part Status: Under Review; Type: Non Component; Vendor: NON_COMPONENT; Vendor Part Number: CE_LABEL; Vendor Part Status: Active
LBL5 = LABEL_FOR_EVALUATOIN_ONLY: NON COMPONENT, LABEL, FOR EVALUATION ONLY, NOT FCC APPROVED FOR RESALE; Additional Datasheet URL: N/A; AutoDoc File: https://notefied-dynamic-precision.com/DB/Apps/Desktop/Item/Object.aspx?id=115268; BU Name: TEXAS INSTRUMENTS NORWAY; Country of Origin: Missing Info; Datasheet URL: N/A; Mass: N/A; Maximum Operating Temperature: N/A; Minimum Operating Temperature: N/A; Mounting Type: NOT APPLY; NOTEfied URL: https://notefied-dynamic-precision.com/NOTEfiedWebInterface/part/show?partNumber=19-00830; Notes: Custom Item; Packing Size: N/A; Packing Type: Missing Info; Part Number: 19-00830; Part Type: Non Component|LABEL; REACH/SVHC Compliance: Missing Info; REACH/SVHC Details: N/A; REACH/SVHC Source: N/A; REACH/SVHC Status: Missing Info; ROHS: Not Applicable; Revision: R033; Status: Released; Texas Part Status: Under Review; Type: Non Component; Vendor: NON_COMPONENT; Vendor Part Status: Active
PCB1 = PCB_V2: NON COMPONENT, PCB, TEXAS INSTRUMENTS; Additional Datasheet URL: https://www.ti.com/; Country of Origin: Missing Info; Datasheet URL: N/A; Mass: N/A; Mounting Type: NOT APPLY; NOTEfied URL: https://notefied-dynamic-precision.com/NOTEfiedWebInterface/part/show?partNumber=19-00925; Notes: Custom PCB outline.; Packing Size: N/A; Packing Type: Missing Info; Part Number: 19-00925; Part Type: Non Component|PCB; ROHS: Not Applicable; Revision: R030; Status: Released; Texas Part Status: Under Review; Type: Non Component; Vendor: TEXAS INSTRUMENTS; Vendor Part Status: Active

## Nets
12V: C23.1 P4.1 U3.1(IN) U3.2(EN)
GND: C23.2 C24.2 C25.2 C26.2 C27.2 C28.2 C29.2 CR2.1(C) CR3.1(C) CR4.4(GND) P4.2 P6.3 P6.5 P6.9 R11.2 TP3.1 U3.6(EGP/GND) U4.2(GND) ; also on sheet 1
VDDS: C29.1 CR4.8(VCC) R10.2 R12.1 ; also on sheet 1
CANH: P2.2 R4.1 R5.2
CANL: P2.1 R6.2 R7.1
DIO1: P3.1 ; also on sheet 1
DIO2: P3.2 ; also on sheet 1
DIO3: P5.1 ; also on sheet 1
DIO4: P5.2 ; also on sheet 1
DIO5: P5.3 ; also on sheet 1
DIO7: P5.4 ; also on sheet 1
DIO9_SWDIO: CR4.7(IO6) P6.2 R10.1 ; also on sheet 1
DIO10_SWDCK: CR4.6(IO5) P6.4 R11.1 ; also on sheet 1
DIO11: U4.5(SHDN) ; also on sheet 1
DIO12: R8.2 ; also on sheet 1
DIO15: U4.8(STB) ; also on sheet 1
DIO16: R9.2 ; also on sheet 1
DIO17: U4.1(TXD) ; also on sheet 1
DIO18: U4.4(RXD) ; also on sheet 1
DIO19: TP1.1 ; also on sheet 1
DIO20: TP2.1 ; also on sheet 1
RSTN: CR4.3(IO3) P6.10 ; also on sheet 1
WMCU_VDD: P4.3 P6.1 R3.1 ; also on sheet 1
N3628058: CR2.2(A) R8.1
N3628062: CR3.2(A) R9.1
N3908284: C25.1 C26.1 C27.1 R12.2 U4.3(VCC)
N3909171: R4.2 U4.7(CANH)
N3909192: R7.2 U4.6(CANL)
N3936704: C28.1 R5.1 R6.1
N3946492: C24.1 R3.2 U3.5(OUT)

Not connected (* = marked no-connect by the designer): CR4 1(IO1)* 2(IO2)* 5(IO4)*; FIDU1 1*; FIDU2 1*; FIDU3 1*; FIDU4 1*; FIDU5 1*; FIDU6 1*; P6 6* 7* 8*; U3 4(DNC)

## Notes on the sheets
sheet 2
- BoosterPack Headers and Peripherals
- LDO
- R3 should be mounted when using 12V supply
- TCAN
- Buttons / LEDs
- Green LED
- Red LED
- DIO3 -> SPI0CLK
  DIO4 -> SPI0PICO/POCI
  DIO5 -> SPI0POCI/PICO
  DIO7 -> SPI0CSN
- CAN FD header
- UART header
- SPI header
- Power supply header
sheet 3
- XDS110 Debugger Interface
- DEBUG
- Use P6 for debugging
  the wireless MCU with
  an external debugger or
  for powering the board
sheet 4
- Mechanical
- Labels
- PCB
- Fiducials
